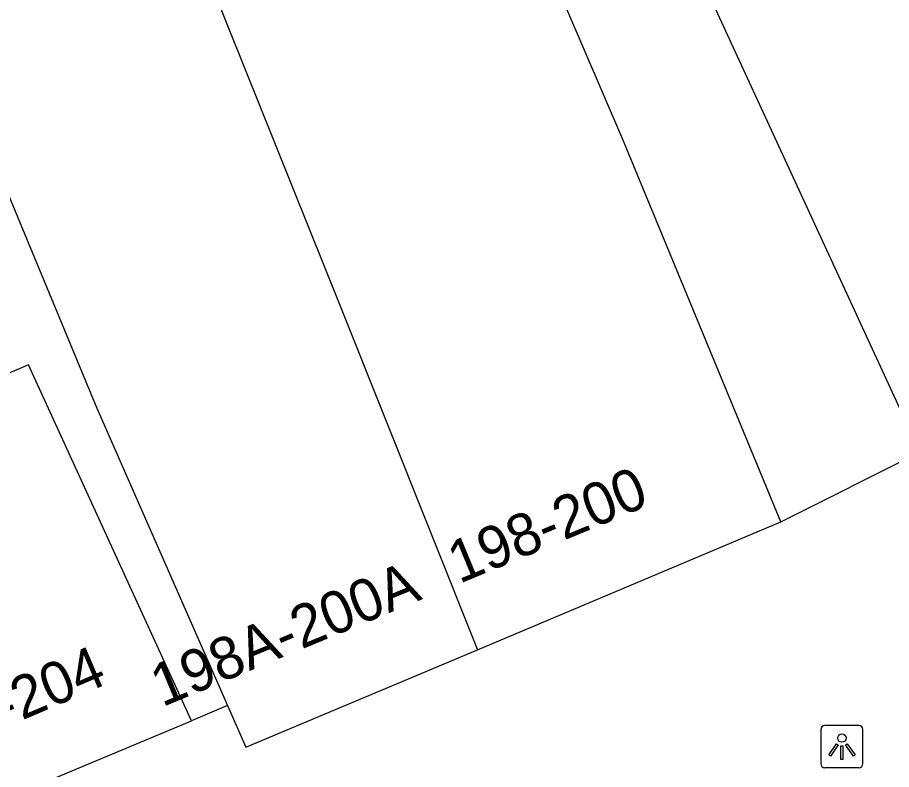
# Model space of a CAD drawing. Extents: x 159265 to 160143, y 383413 to 384319.
# Drawn here: x 159593.13 to 159613.82, y 383562.77 to 383580.55 of the extents above; entities that cross this region are included whole.
import ezdxf

# ---------------------------------------------------------------- set-up
doc = ezdxf.new("R2010")
doc.units = 0
for name, color, linetype in [('IMGEO_Lichtpunt', 7, 'Continuous'), ('IMGEO_Pand', 7, 'Continuous'), ('IMGEO_Pand_nummerreeks', 7, 'Continuous'), ('IMGEO_Rijbaan_lokaal_open', 7, 'Continuous'), ('IMGEO_Voetpad_open', 7, 'Continuous')]:
    doc.layers.add(name, color=color, linetype=linetype)

msp = doc.modelspace()

# ---------------------------------------------------------------- linework, layer by layer
at = {"layer": 'IMGEO_Lichtpunt'}
for p, q in [((159612.144, 383563.711), (159612.144, 383562.904)), ((159612.144, 383563.711), (159612.144, 383562.904)), ((159613.046, 383563.806), (159612.238, 383563.806)), ((159613.046, 383563.806), (159612.238, 383563.806)), ((159613.14, 383562.904), (159613.14, 383563.711)), ((159613.14, 383562.904), (159613.14, 383563.711)), ((159612.238, 383562.81), (159613.046, 383562.81)), ((159612.238, 383562.81), (159613.046, 383562.81))]:
    msp.add_line(p, q, dxfattribs=at)
for points in [[(159612.518, 383563.375), (159612.557, 383563.347), (159612.369, 383563.085), (159612.331, 383563.112), (159612.518, 383563.375)], [(159612.62, 383563.327), (159612.667, 383563.327), (159612.667, 383563.005), (159612.62, 383563.005), (159612.62, 383563.327)], [(159612.73, 383563.347), (159612.768, 383563.374), (159612.955, 383563.112), (159612.916, 383563.084), (159612.73, 383563.347)]]:
    msp.add_lwpolyline(points, dxfattribs=at)
msp.add_circle((159612.643, 383563.509), 0.0994, dxfattribs=at)
for centre, start, end in [((159612.238, 383563.711), 90, 180), ((159612.238, 383563.711), 90, 180), ((159613.046, 383563.711), 0, 90), ((159613.046, 383563.711), 0, 90), ((159612.238, 383562.904), 180, 270), ((159612.238, 383562.904), 180, 270), ((159613.046, 383562.904), 270, 0), ((159613.046, 383562.904), 270, 360)]:
    msp.add_arc(centre, 0.0946, start, end, dxfattribs=at)
at = {"layer": 'IMGEO_Pand'}
for points in [[(159608.659, 383597.35), (159604.887, 383595.655), (159609.507, 383581.069), (159614.49, 383570.268)], [(159611.199, 383568.622), (159607.455, 383577.664), (159601.127, 383592.412), (159599.929, 383595.303), (159598.584, 383594.73)], [(159593.928, 383590.754), (159585.134, 383587.106), (159587.556, 383582.99), (159589.785, 383583.914), (159595.01, 383571.313), (159598.106, 383564.278)], [(159593.928, 383590.754), (159600.778, 383573.706), (159604.021, 383565.6)], [(159597.249, 383563.919), (159593.397, 383572.335), (159591.049, 383571.337), (159589.625, 383574.687), (159587.14, 383573.63)], [(159604.021, 383565.6), (159611.199, 383568.622)], [(159598.106, 383564.278), (159598.54, 383563.293), (159604.021, 383565.6)], [(159592.174, 383561.793), (159597.249, 383563.919)]]:
    msp.add_lwpolyline(points, dxfattribs=at)
at = {"layer": 'IMGEO_Rijbaan_lokaal_open'}
msp.add_lwpolyline([(159611.199, 383568.622), (159614.49, 383570.268)], dxfattribs=at)
at = {"layer": 'IMGEO_Voetpad_open'}
msp.add_lwpolyline([(159598.106, 383564.278), (159597.249, 383563.919)], dxfattribs=at)

# ---------------------------------------------------------------- texts
at = {"layer": 'IMGEO_Pand_nummerreeks'}
for s, rotation, p in [('198-200', 22.523, (159603.588, 383567.154)), ('198A-200A', 22.5287, (159596.557, 383564.237)), ('202-204', 23.2105, (159590.782, 383562.87))]:
    msp.add_text(s, height=1, rotation=rotation, dxfattribs=at).set_placement(p)

doc.saveas('drawing.dxf')
